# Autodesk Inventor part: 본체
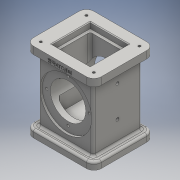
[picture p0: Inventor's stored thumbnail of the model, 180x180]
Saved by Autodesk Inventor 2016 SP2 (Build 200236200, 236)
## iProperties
Created: 2017-08
Part Number: 본체
Material: Generic
Document SubType Name: Modeling
Designer: Administrator
Density: 1 g/cm^3
Appearance: Default
Mass: 322.201 g
Surface Area: 648.794 cm^2
Volume: 322.201 cm^3
Author: Administrator
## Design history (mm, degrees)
sketch "스케치1"
  geometry: L1 (0, 0)-(92, 0); L2 (92, 0)-(92, -82); L3 (92, -82)-(0, -82); L4 (0, -82)-(0, 0)
  constraints: 8 end point, 2 parallel, 1 horizontal, 1 perpendicular
  dimensions: "d0" = 92 distance between parallel lines of L2 L4; "d1" = 82 distance between parallel lines of L3 L1
extrude "돌출1" new body sketch "스케치1" distance "d2" = 10; taper "d3" = 0 deg
sketch "스케치3"
  geometry: L1 (9, -8)-(83, -8); L2 (83, -8)-(83, -74); L3 (83, -74)-(9, -74); L4 (9, -74)-(9, -8); L5 (46, 14.875)-(46, -113.315); L6 (-13.466, -41)-(112.053, -41); L7 (92, 0)-(0, 0) reference; L8 (0, 0)-(0, -82) reference; 2 further points
  constraints: 12 end point, 2 horizontal, 2 midpoint, 2 parallel, 2 point on line, 1 perpendicular, 1 vertical, 2 other
  dimensions: "d6" = 74 distance between parallel lines of L2 L4; "d7" = 66 distance between parallel lines of L3 L1
extrude "돌출2" join sketch "스케치3" distance "d8" = 88; taper "d9" = 0 deg
sketch "스케치4"
  geometry: L1 (0, 0)-(0, -82) reference; L2 (92, -82)-(92, 0) reference; L3 (0, 0)-(92, 0); L4 (92, 0)-(92, -82); L5 (92, -82)-(0, -82); L6 (0, -82)-(0, 0)
  constraints: 8 end point, 2 parallel, 1 horizontal, 1 perpendicular
extrude "돌출3" join sketch "스케치4" distance "d10" = 10; taper "d11" = 0 deg
sketch "스케치5"
  geometry: L1 (-22, -65)-(-70, -65); L2 (-70, -65)-(-70, -17); L3 (-70, -17)-(-22, -17); L4 (-22, -17)-(-22, -65); L5 (-46, -97.263)-(-46, 16.227); L6 (13.409, -41)-(-111.741, -41); L7 (-92, -82)-(0, -82) reference; L8 (0, -82)-(0, 0) reference; 2 further points
  constraints: 12 end point, 2 horizontal, 2 midpoint, 2 parallel, 2 point on line, 1 perpendicular, 1 vertical, 2 other
  dimensions: "d12" = 48 distance between parallel lines of L2 L4; "d13" = 48 distance between parallel lines of L3 L1
extrude "돌출4" cut sketch "스케치5" distance "d14" = 16; taper "d15" = 0 deg
sketch "스케치6"
  geometry: L1 (83, -10)-(-9, -10) reference; C1 r 35 at (37, 44); 1 further point
  constraints: 1 centre point, 1 midpoint, 1 vertical alignment
  dimensions: "d16" = 70 diameter of C1; "d17" = 54 distance from line of L1 C1.centre
extrude "돌출5" cut sketch "스케치6" distance "d18" = 3; taper "d19" = 0 deg
sketch "스케치7"
  geometry: L1 (-9, 10)-(83, 10) reference; C1 r 35 at (37, -44); 1 further point
  constraints: 1 centre point, 1 midpoint, 1 vertical alignment
  dimensions: "d20" = 70 diameter of C1; "d21" = 54 distance from line of L1 C1.centre
extrude "돌출6" cut sketch "스케치7" distance "d22" = 3; taper "d23" = 0 deg
sketch "스케치8"
  geometry: L1 (46, -54)-(-46, -54) reference; C1 r 24 at (0, 2); 1 further point
  constraints: 1 centre point, 1 midpoint, 1 vertical alignment
  dimensions: "d24" = 48 diameter of C1; "d25" = 56 distance from line of L1 C1.centre
extrude "돌출7" cut sketch "스케치8" stored distance "d26" = 3; taper "d27" = 0 deg
sketch "스케치9"
  geometry: L1 (20, -15)-(72, -15); L2 (72, -15)-(72, -67); L3 (72, -67)-(20, -67); L4 (20, -67)-(20, -15); L5 (46, 9.933)-(46, -105.516); L6 (-12.497, -41)-(110.193, -41); L7 (92, 0)-(0, 0) reference; L8 (0, 0)-(0, -82) reference; 2 further points
  constraints: 12 end point, 2 horizontal, 2 midpoint, 2 parallel, 2 point on line, 1 perpendicular, 1 vertical, 2 other
  dimensions: "d28" = 52 distance between parallel lines of L3 L1; "d29" = 52 distance between parallel lines of L2 L4
extrude "돌출8" cut sketch "스케치9" distance "d30" = 8; taper "d31" = 0 deg
sketch "스케치10"
  geometry: L1 (24, -19)-(68, -19); L2 (68, -19)-(68, -63); L3 (68, -63)-(24, -63); L4 (24, -63)-(24, -19); L5 (46, 16.944)-(46, -107.049); L6 (-13.372, -41)-(115.449, -41); L7 (92, 0)-(0, 0) reference; L8 (0, 0)-(0, -82) reference; 2 further points
  constraints: 12 end point, 2 horizontal, 2 midpoint, 2 parallel, 2 point on line, 1 perpendicular, 1 vertical, 2 other
  dimensions: "d32" = 44 distance of L1.start L1.end; "d33" = 44 distance between parallel lines of L3 L1
extrude "돌출9" cut sketch "스케치10" distance "d34" = 74; taper "d35" = 0 deg
sketch "스케치12"
  geometry: L1 (46, -54)-(-46, -54) reference; A1 r 29 centre (0, 2) between (0, 31) and (29, 2); 3 further points
  constraints: 4 point on circle, 3 vertical alignment, 2 horizontal alignment, 1 centre point, 1 midpoint
  dimensions: "d36" = 58 diameter of A1; "d37" = 56 distance from line of L1 A1.centre
hole "구멍1" sketch "스케치12" at (0, 31), (29, 2), (-29, 2), (0, -27) diameter "d38" = 3.242; stored, may be unused: countersink angle "d42" = 90 deg, drill point angle "d44" = 118 deg; dims "d39" = 4, "d40" = 4, "d41" = 2, "d43" = 6
sketch "스케치13"
  geometry: L1 (-46, 54)-(46, 54) reference; C1 r 29 at (0, -2); C2 r 1.621 at (0, -31) reference; C3 r 1.621 at (-29, -2) reference; C4 r 1.621 at (29, -2) reference; C5 r 1.621 at (0, 27) reference; 5 further points
  constraints: 4 coincident, 1 centre point, 1 midpoint, 1 vertical alignment
  dimensions: "d45" = 58 diameter of C1; "d46" = 56 distance from line of L1 C1.centre
hole "구멍2" sketch "스케치13" at (0, -31), (-29, -2), (29, -2), (0, 27) diameter "d47" = 3.242; stored, may be unused: countersink angle "d51" = 90 deg, drill point angle "d53" = 118 deg; dims "d48" = 4, "d49" = 4, "d50" = 2, "d52" = 6
sketch "스케치14"
  geometry: L1 (10, 74)-(10, -8) reference; 5 further points
  constraints: 4 midpoint, 3 horizontal alignment
  dimensions: "d54" = 38 distance from line of L1 point (-28, 33)
hole "구멍3" sketch "스케치14" at (-28, 33) diameter "d56" = 4.134; stored, may be unused: countersink angle "d60" = 90 deg, drill point angle "d62" = 118 deg; dims "d57" = 10, "d58" = 4, "d59" = 2, "d61" = 14.2
sketch "스케치15"
  geometry: L1 (10, 74)-(10, -8) reference; 2 further points
  constraints: 1 horizontal alignment, 1 midpoint
  dimensions: "d63" = 80 distance from line of point (-70, 33) L1
hole "구멍4" sketch "스케치15" at (-70, 33) diameter "d64" = 4.134; stored, may be unused: countersink angle "d68" = 90 deg, drill point angle "d70" = 118 deg; dims "d65" = 10, "d66" = 4, "d67" = 2, "d69" = 14.2
sketch "스케치16"
  geometry: L1 (46, 21.815)-(46, -83.748); L2 (-19.316, -41)-(104.246, -41); L3 (92, 0)-(0, 0) reference; L4 (0, 0)-(0, -82) reference; 6 further points
  constraints: 4 end point, 2 midpoint, 2 point on line, 2 vertical alignment, 1 horizontal, 1 symmetric about line, 1 vertical
  dimensions: "d75" = 72 distance of point (82, -10.06) point (10, -10.06); "d76" = 62 distance of point (10, -72.06) point (10, -10.06); "d77" = 62 distance of point (82, -72.06) point (82, -10.06)
hole "구멍5" sketch "스케치16" at (10, -10.06), (82, -10.06), (82, -72.06), (10, -72.06) diameter "d78" = 3.242; stored, may be unused: countersink angle "d82" = 90 deg, drill point angle "d84" = 118 deg; dims "d79" = 4, "d80" = 4, "d81" = 2, "d83" = 6
sketch "스케치17"
  geometry: C1 r 1.621 at (-10, -72.06) reference; C2 r 1.621 at (-82, -72.06) reference; C3 r 1.621 at (-10, -10.06) reference; C4 r 1.621 at (-82, -10.06) reference; 5 further points
  constraints: 4 coincident
hole "구멍6" sketch "스케치17" at (-10, -72.06), (-82, -72.06), (-10, -10.06), (-82, -10.06) diameter "d85" = 3.242; stored, may be unused: countersink angle "d89" = 90 deg, drill point angle "d91" = 118 deg; dims "d86" = 4, "d87" = 4, "d88" = 2, "d90" = 6
sketch "스케치18"
  geometry: L1 (0, 0)-(0, 10) reference; L2 (92, 0)-(0, 0) reference; 3 further points
  constraints: 1 coincident, 1 other
  dimensions: "d92" = 46 distance from line of point (46, 4) L1; "d93" = 4 distance from line of point (46, 4) L2
feature "엠보싱1" sketch "스케치18" dims "d0" = 92, "d1" = 82, "d94" = 0.5, "d95" = 0
fillet "모깎기1" dims "d96" = 10
fillet "모깎기3" dims "d101" = 3
fillet "모깎기4" dims "d102" = 3
fillet "모깎기5" dims "d103" = 3
fillet "모깎기6" dims "d104" = 3
chamfer "모따기2" distance "d106" = 1; stored, may be unused: second distance "d107" = 2, angle "d108" = 45 deg
fillet "모깎기8" dims "d109" = 3
node "솔리드1"
